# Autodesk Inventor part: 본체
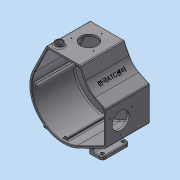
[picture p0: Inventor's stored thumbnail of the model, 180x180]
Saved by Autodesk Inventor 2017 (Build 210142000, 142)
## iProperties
Created: 2017-05
Part Number: 본체
Material: 알루미늄 6061
Document SubType Name: Modeling
Designer: mduedu
Density: 2.71 g/cm^3
Appearance: 기본값
Mass: 1345.72 g
Surface Area: 1824.08 cm^2
Volume: 496.576 cm^3
Author: mduedu
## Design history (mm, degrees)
sketch "스케치1"
  geometry: L1 (-71.801, 35.28)-(-40, 100); L2 (-40, 100)-(40, 100); L3 (40, 100)-(59.768, 59.768); L4 (59.768, 59.768)-(100, 40); L5 (100, 40)-(100, -40); L6 (100, -40)-(35.28, -71.801); A1 r 80 centre (0, 0) between (-71.801, 35.28) and (35.28, -71.801); 3 further points
  constraints: 12 end point, 4 tangent, 2 midpoint, 2 point on circle, 1 centre point, 1 coincident, 1 horizontal, 1 horizontal alignment, 1 perpendicular, 1 vertical alignment
  dimensions: "d0" = 160 diameter of A1; "d2" = 100 distance from line of L2 point (0, 0); "d3" = 100 distance from line of L5 point (0, 0); "d4" = 80 distance of L1.end L2.end; "d5" = 80 distance of L4.end L5.end
extrude "돌출1" new body sketch "스케치1" distance "d6" = 5; taper "d7" = 0 deg
fillet "모깎기1" dims "d8" = 50
sketch "스케치2"
  geometry: C1 r 22 at (0, 0); 1 further point
  constraints: 1 centre point, 1 coincident
  dimensions: "d9" = 44 diameter of C1
extrude "돌출2" join sketch "스케치2" distance "d10" = 22.5; taper "d11" = 0 deg
sketch "스케치3"
  geometry: C1 r 18.5 at (0, 0); 1 further point
  constraints: 1 centre point, 1 coincident
  dimensions: "d12" = 37 diameter of C1
extrude "돌출3" cut sketch "스케치3" distance "d13" = 9; taper "d14" = 0 deg
fillet "모깎기2" dims "d15" = 3
sketch "스케치4"
  geometry: L1 (35.28, -71.801)-(100, -40) reference; L2 (100, -40)-(100, 40) reference; L3 (100, 40)-(75.073, 52.248) reference; L4 (52.248, 75.073)-(40, 100) reference; L5 (40, 100)-(-40, 100) reference; L6 (-40, 100)-(-71.801, 35.28) reference; L7 (-36.886, 95)-(36.886, 95); L8 (36.886, 95)-(47.76, 72.868); L9 (72.868, 47.76)-(95, 36.886); L10 (95, 36.886)-(95, -36.886); L11 (95, -36.886)-(33.075, -67.313); L12 (-67.313, 33.075)-(-36.886, 95); C1 r 25 at (0, 0) reference; A1 r 50 centre (97.123, 97.123) between (52.248, 75.073) and (75.073, 52.248) reference; A2 r 80 centre (0, 0) between (-71.801, 35.28) and (35.28, -71.801) reference; A3 r 55 centre (97.123, 97.123) between (47.76, 72.868) and (72.868, 47.76); A4 r 75 centre (0, 0) between (-67.313, 33.075) and (33.075, -67.313); 1 further point
  constraints: 12 end point, 4 point on circle, 2 centre point, 7 other
  dimensions: "d16" = 5 distance between parallel lines of L7 L5
extrude "돌출4" join sketch "스케치4" distance "d17" = 100; taper "d18" = 0 deg
sketch "스케치5"
  geometry: L1 (80, 0)-(0, 0) reference; C1 r 20 at (40, -45); 2 further points
  constraints: 1 centre point, 1 midpoint, 1 vertical alignment
  dimensions: "d19" = 40 diameter of C1; "d21" = 45 distance from line of C1.centre L1
extrude "돌출5" cut sketch "스케치5" stored distance "d22" = 100; taper "d23" = 0 deg
sketch "스케치6"
  geometry: L1 (0, 0)-(0, -105) reference; L2 (80, -105)-(0, -105) reference; C1 r 9 at (14, -89); 1 further point
  constraints: 1 centre point
  dimensions: "d24" = 18 diameter of C1; "d26" = 14 distance from line of C1.centre L1; "d27" = 16 distance from line of C1.centre L2
extrude "돌출6" join sketch "스케치6" distance "d28" = 7; taper "d29" = 0 deg
hole "구멍1" diameter "d32" = 14; stored, may be unused: countersink angle "d36" = 90 deg, drill point angle "d38" = 118 deg; dims "d33" = 6, "d34" = 4, "d35" = 2, "d37" = 8, "d39" = 10, "d40" = 10
sketch "스케치7"
  geometry: L1 (-105, 0)-(-105, 80) reference; L2 (0, 0)-(0, 80) reference; C1 r 20 at (-70, 40); 2 further points
  constraints: 1 centre point, 1 horizontal alignment, 1 midpoint
  dimensions: "d41" = 40 diameter of C1; "d42" = 35 distance from line of C1.centre L1
extrude "돌출7" cut sketch "스케치7" stored distance "d43" = 7; taper "d44" = 0 deg
node "작업 평면1"
sketch "스케치8"
  geometry: L1 (47.76, 72.868)-(36.886, 95) reference; L2 (36.886, 95)-(-36.886, 95) reference; L3 (-36.886, 95)-(-67.313, 33.075) reference; L4 (33.075, -67.313)-(95, -36.886) reference; L5 (95, -36.886)-(95, 36.886) reference; L6 (95, 36.886)-(72.868, 47.76) reference; L7 (95, 36.886)-(95, -36.886) reference; L8 (-36.886, 95)-(36.886, 95) reference; L9 (36.886, 95)-(47.76, 72.868) reference; L10 (-71, 4)-(-74.893, 4); L11 (-71, -4)-(-74.893, -4); L12 (-4, -71)-(-4, -74.893); L13 (4, -71)-(4, -74.893); L14 (30.394, 91)-(30.394, 95); L15 (34.394, 87)-(40.817, 87); L16 (30.394, 95)-(36.886, 95); L17 (36.886, 95)-(37.984, 92.764); L18 (91, 30.394)-(95, 30.394); L19 (87, 34.394)-(87, 40.817); L20 (87, 40.817)-(95, 36.886); L21 (95, 36.886)-(95, 30.394); C1 r 25 at (0, 0) reference; A1 r 75 centre (0, 0) between (-67.313, 33.075) and (33.075, -67.313) reference; A2 r 55 centre (97.123, 97.123) between (47.76, 72.868) and (72.868, 47.76) reference; A3 r 4 centre (-71, 0) between (-71, 4) and (-71, -4); A4 r 4 centre (0, -71) between (-4, -71) and (4, -71); A5 r 4 centre (34.394, 91) between (30.394, 91) and (34.394, 87); A6 r 75 centre (0, 0) between (-67.313, 33.075) and (33.075, -67.313) reference; A7 r 4 centre (91, 34.394) between (91, 30.394) and (87, 34.394); 1 further point
  constraints: 24 end point, 17 point on circle, 14 tangent, 5 point on line, 4 centre point, 3 equal radius, 3 perpendicular, 3 vertical, 2 collinear, 2 horizontal, 1 horizontal alignment, 1 parallel, 1 vertical alignment
  dimensions: "d46" = 8 diameter of A3
extrude "돌출8" join sketch "스케치8" stored distance "d49" = 7; taper "d50" = 0 deg
node "작업 평면2"
sketch "스케치9"
  geometry: L1 (71.801, 0)-(71.801, 105) reference; L2 (71.801, 0)-(-35.28, 0) reference; L3 (-35.28, 0)-(-35.28, 105) reference; L4 (71.801, 105)-(-35.28, 105) reference; L5 (40, 0)-(40, 105) reference; L6 (71.801, 52.5)-(-35.28, 52.5); L7 (71.801, 20)-(40, 20); L8 (40, 20)-(40, 85); L9 (40, 85)-(71.801, 85); L10 (71.801, 85)-(71.801, 20); 1 further point
  constraints: 10 end point, 2 midpoint, 2 parallel, 2 point on line, 1 horizontal, 1 perpendicular, 1 other
  dimensions: "d52" = 20 distance between parallel lines of L7 L2
extrude "돌출9" join sketch "스케치9" distance "d53" = 8; taper "d54" = 0 deg
fillet "모깎기3" dims "d55" = 8
sketch "스케치10"
  geometry: C1 r 4 at (-63.801, -28); C2 r 4 at (-63.801, -77); A1 r 8 centre (-63.801, -28) between (-63.801, -20) and (-71.801, -28) reference; A2 r 8 centre (-63.801, -77) between (-71.801, -77) and (-63.801, -85) reference; 1 further point
  constraints: 2 centre point, 2 coincident, 1 equal radius
  dimensions: "d56" = 8 diameter of C1
extrude "돌출10" cut sketch "스케치10" stored distance "d57" = 50.5; taper "d58" = 0 deg
sketch "스케치11"
  geometry: L1 (-63.801, -20)-(-40, -20) reference; L2 (-40, -20)-(-40, -85) reference; L3 (-40, -85)-(-63.801, -85) reference; L4 (-71.801, -77)-(-71.801, -28) reference; L5 (71.801, -77)-(71.801, -28) reference; L6 (40, -85)-(63.801, -85) reference; L7 (40, -20)-(40, -85) reference; L8 (63.801, -20)-(40, -20) reference; L9 (-40, -85)-(-48, -85); L10 (-48, -85)-(-48, -20); L11 (-48, -20)-(-40, -20); L12 (-40, -20)-(-40, -85); L13 (40, -85)-(48, -85); L14 (48, -85)-(48, -20); L15 (48, -20)-(40, -20); L16 (40, -20)-(40, -85); C1 r 4 at (-63.801, -28) reference; C2 r 4 at (-63.801, -77) reference; C3 r 4 at (63.801, -28) reference; C4 r 4 at (63.801, -77) reference; A1 r 8 centre (-63.801, -28) between (-63.801, -20) and (-71.801, -28) reference; A2 r 8 centre (-63.801, -77) between (-71.801, -77) and (-63.801, -85) reference; A3 r 8 centre (63.801, -28) between (71.801, -28) and (63.801, -20) reference; A4 r 8 centre (63.801, -77) between (63.801, -85) and (71.801, -77) reference; 1 further point
  constraints: 16 end point, 4 parallel, 2 horizontal, 2 perpendicular, 2 point on line
  dimensions: "d59" = 8 distance of L10.end L11.end; "d61" = 8 distance of L14.end L15.end
extrude "돌출11" join sketch "스케치11" stored distance "d62" = 5; taper "d63" = 0 deg
fillet "모깎기4" dims "d64" = 5
fillet "모깎기5" dims "d65" = 2
fillet "모깎기6" dims "d66" = 2
fillet "모깎기8" dims "d68" = 2
fillet "모깎기9" dims "d70" = 3, "d101" = 1
fillet "모깎기10" dims "d71" = 3
fillet "모깎기11" dims "d72" = 3
fillet "모깎기12" dims "d73" = 3
fillet "모깎기13" dims "d76" = 3
chamfer "모따기1" distance "d77" = 0.5; stored, may be unused: second distance "d78" = 2, angle "d79" = 45 deg
chamfer "모따기2" distance "d87" = 1; stored, may be unused: second distance "d88" = 2, angle "d89" = 45 deg
chamfer "모따기3" distance "d90" = 1; stored, may be unused: second distance "d91" = 2, angle "d92" = 45 deg
sketch "스케치14"
  geometry: 3 further points
  constraints: 3 other
hole "구멍2" sketch "스케치14" at (-55.375, -40), (-3.414, -40), (-29.394, -85) diameter "d93" = 2.459; stored, may be unused: countersink angle "d97" = 90 deg, drill point angle "d99" = 0 deg; dims "d94" = 6, "d95" = 4, "d96" = 2, "d98" = 8
sketch "스케치15"
  geometry: 3 further points
  constraints: 3 other
hole "구멍4" sketch "스케치15" at (-55.981, -14.394), (-4.019, -14.394), (-30, -59.394) diameter "d102" = 2.459; stored, may be unused: countersink angle "d106" = 90 deg, drill point angle "d108" = 0 deg; dims "d103" = 6, "d104" = 4, "d105" = 2, "d107" = 8
sketch "스케치16"
  geometry: 4 further points
  constraints: 4 other
hole "구멍6" sketch "스케치16" at (0, -71), (91, 34.394), (34.394, 91), (-71, 0) diameter "d109" = 2.459; stored, may be unused: countersink angle "d113" = 90 deg, drill point angle "d115" = 120 deg; dims "d110" = 8.5, "d111" = 4, "d112" = 2, "d114" = 10
node "작업 평면4"
sketch "스케치17"
  geometry: 2 further points
  constraints: 1 horizontal alignment, 1 other
  dimensions: "d116" = 52.5 distance of point (0, 16.14) point (52.5, 16.14)
feature "엠보싱2" sketch "스케치17" dims "d117" = 0.5, "d118" = 0
node "솔리드1"
mirror "대칭1"
node "투영된 루프1"
node "투영된 루프2"
node "투영된 루프3"
node "투영된 루프4"
node "투영된 루프5"
other parameters: "d45" = 95
